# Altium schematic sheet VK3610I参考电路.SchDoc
size A4
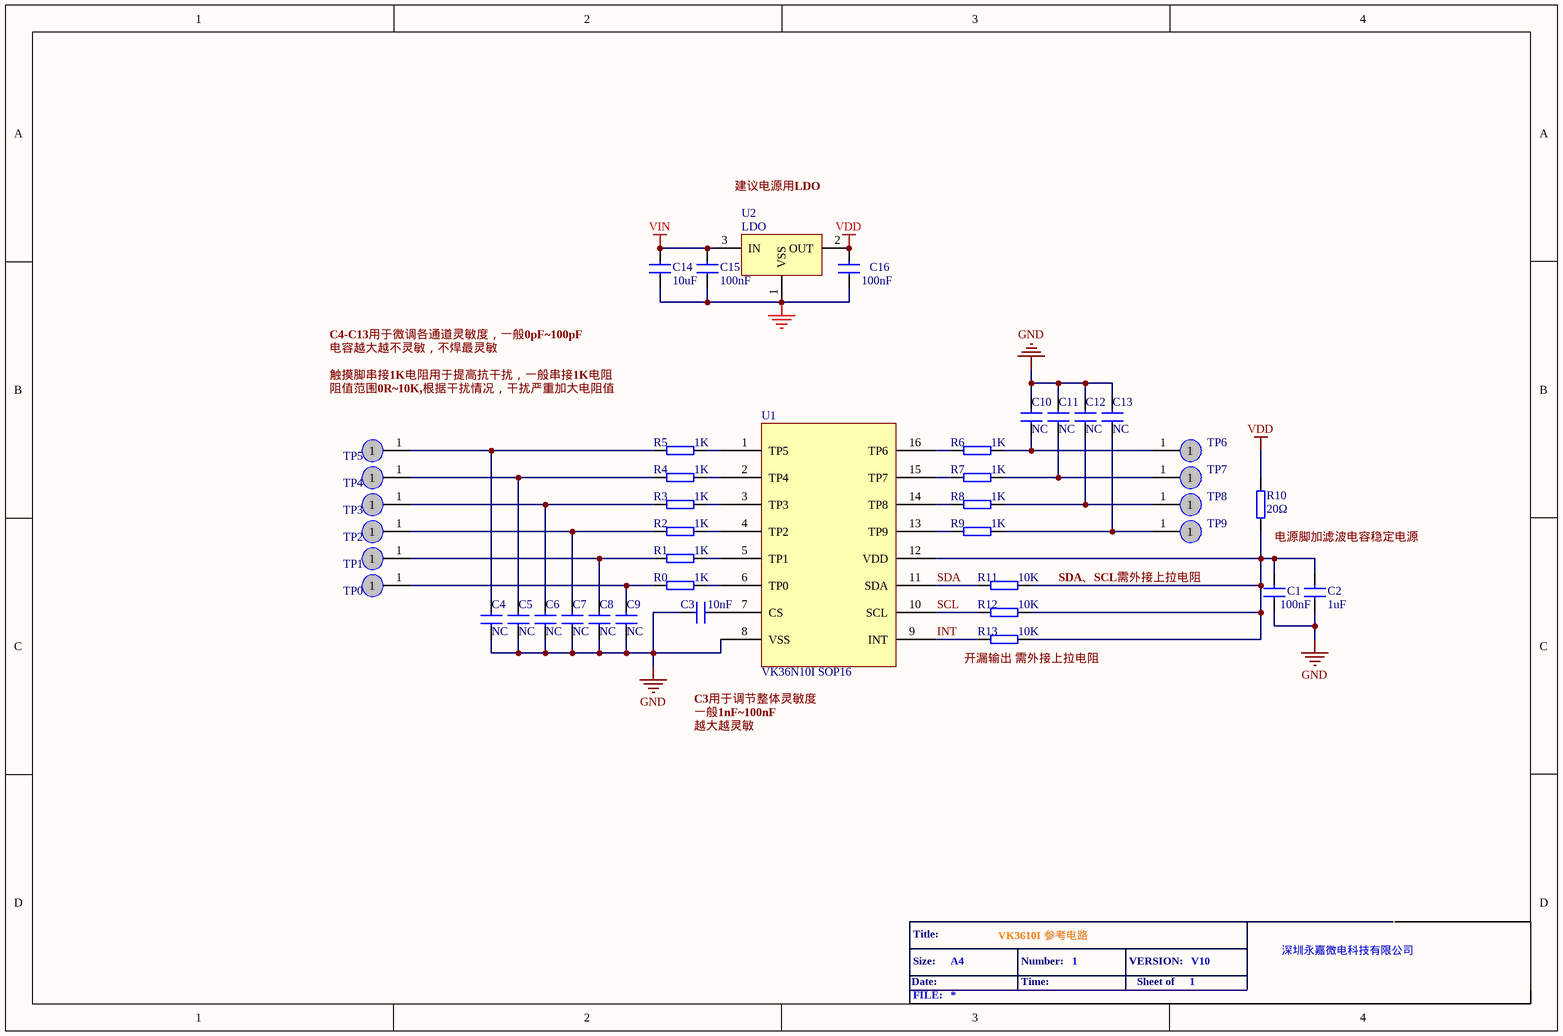
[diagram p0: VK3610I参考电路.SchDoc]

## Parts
C1  100nF  [0603-C]
C2  value 1uF  [0603-C]  (hidden comment: 10uF)
C3  value 10nF  [0603-C]  (hidden comment: 10uF)
C4  value NC  [0603-C]  (hidden comment: 10uF)
C5  value NC  [0603-C]  (hidden comment: 10uF)
C6  value NC  [0603-C]  (hidden comment: 10uF)
C7  value NC  [0603-C]  (hidden comment: 10uF)
C8  value NC  [0603-C]  (hidden comment: 10uF)
C9  value NC  [0603-C]  (hidden comment: 10uF)
C10  value NC  [0603-C]  (hidden comment: 10uF)
C11  value NC  [0603-C]  (hidden comment: 10uF)
C12  value NC  [0603-C]  (hidden comment: 10uF)
C13  value NC  [0603-C]  (hidden comment: 10uF)
C14  10uF  [0805-C]
C15  100nF  [0805-C]
C16  100nF  [0805-C]
R0  1K  [0603-R]
R1  1K  [0603-R]
R2  1K  [0603-R]
R3  1K  [0603-R]
R4  1K  [0603-R]
R5  1K  [0603-R]
R6  1K  [0603-R]
R7  1K  [0603-R]
R8  1K  [0603-R]
R9  1K  [0603-R]
R10  20Ω  [0603-R]
R11  10K  [0603-R]
R12  10K  [0603-R]
R13  10K  [0603-R]
TP0  TPAD  [TP-PAD0]  (value not drawn)
TP1  TPAD  [TP-PAD0]  (value not drawn)
TP2  TPAD  [TP-PAD0]  (value not drawn)
TP3  TPAD  [TP-PAD0]  (value not drawn)
TP4  TPAD  [TP-PAD0]  (value not drawn)
TP5  TPAD  [TP-PAD0]  (value not drawn)
TP6  TPAD  [TP-PAD0]  (value not drawn)
TP7  TPAD  [TP-PAD0]  (value not drawn)
TP8  TPAD  [TP-PAD0]  (value not drawn)
TP9  TPAD  [TP-PAD0]  (value not drawn)
U1  VK36N10I SOP16
U2  LDO  [SOT-23]

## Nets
GND: C1.2 C2.2 C3.2 C4.1 C5.1 C6.1 C7.1 C8.1 C9.1 C10.2 C11.2 C12.2 C13.2 C14.2 C15.2 C16.2 U1.8(VSS) U2.1(VSS)
VDD: C16.1 R10.1 U2.2(OUT)
VIN: C14.1 C15.1 U2.3(IN)
INT: R13.1 U1.9(INT)
SCL: R12.1 U1.10(SCL)
SDA: R11.1 U1.11(SDA)
NetC1_1: C1.1 C2.1 R10.2 R11.2 R12.2 R13.2 U1.12(VDD)
NetC3_1: C3.1 U1.7(CS)
NetC4_2: C4.2 R5.2 TP5.1
NetC5_2: C5.2 R4.2 TP4.1
NetC6_2: C6.2 R3.2 TP3.1
NetC7_2: C7.2 R2.2 TP2.1
NetC8_2: C8.2 R1.2 TP1.1
NetC9_2: C9.2 R0.1 TP0.1
NetC10_1: C10.1 R6.2 TP6.1
NetC11_1: C11.1 R7.2 TP7.1
NetC12_1: C12.1 R8.2 TP8.1
NetC13_1: C13.1 R9.2 TP9.1
NetR0_2: R0.2 U1.6(TP0)
NetR1_1: R1.1 U1.5(TP1)
NetR2_1: R2.1 U1.4(TP2)
NetR3_1: R3.1 U1.3(TP3)
NetR4_1: R4.1 U1.2(TP4)
NetR5_1: R5.1 U1.1(TP5)
NetR6_1: R6.1 U1.16(TP6)
NetR7_1: R7.1 U1.15(TP7)
NetR8_1: R8.1 U1.14(TP8)
NetR9_1: R9.1 U1.13(TP9)

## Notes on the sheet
- 建议电源用LDO
- 触摸脚串接1K电阻用于提高抗干扰，一般串接1K电阻
- C4-C13用于微调各通道灵敏度，一般0pF
  00pF
- 电容越大越不灵敏，不焊最灵敏
- 阻值范围0R
  0K,根据干扰情况，干扰严重加大电阻值
- SDA、SCL需外接上拉电阻
- (near R10) 电源脚加滤波电容稳定电源
- C3用于调节整体灵敏度
- 一般1nF
  00nF
- (near R13) 开漏输出 需外接上拉电阻
- 越大越灵敏
- Date:
- Title:
- Size:
- A4
- VK3610I 参考电路
- Number:
- Time:
- 1
- VERSION:
- Sheet of
- V10
- 深圳永嘉微电科技有限公司
- FILE:

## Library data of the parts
C1-C16 = CAP: Capacitor
R0-R13 = RES: Resistor
TP0-TP9 = TPAD: TESTING
U2 = V6206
